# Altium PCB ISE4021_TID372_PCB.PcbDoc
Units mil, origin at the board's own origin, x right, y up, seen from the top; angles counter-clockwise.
Board outline 3700 x 2300 mil, 4 copper layers (Top Layer, Internal Plane 1, Mid-Layer 1, Bottom Layer), stack 62.1 mil thick; 57 components, 23 nets, 154 pads, 293 vias.
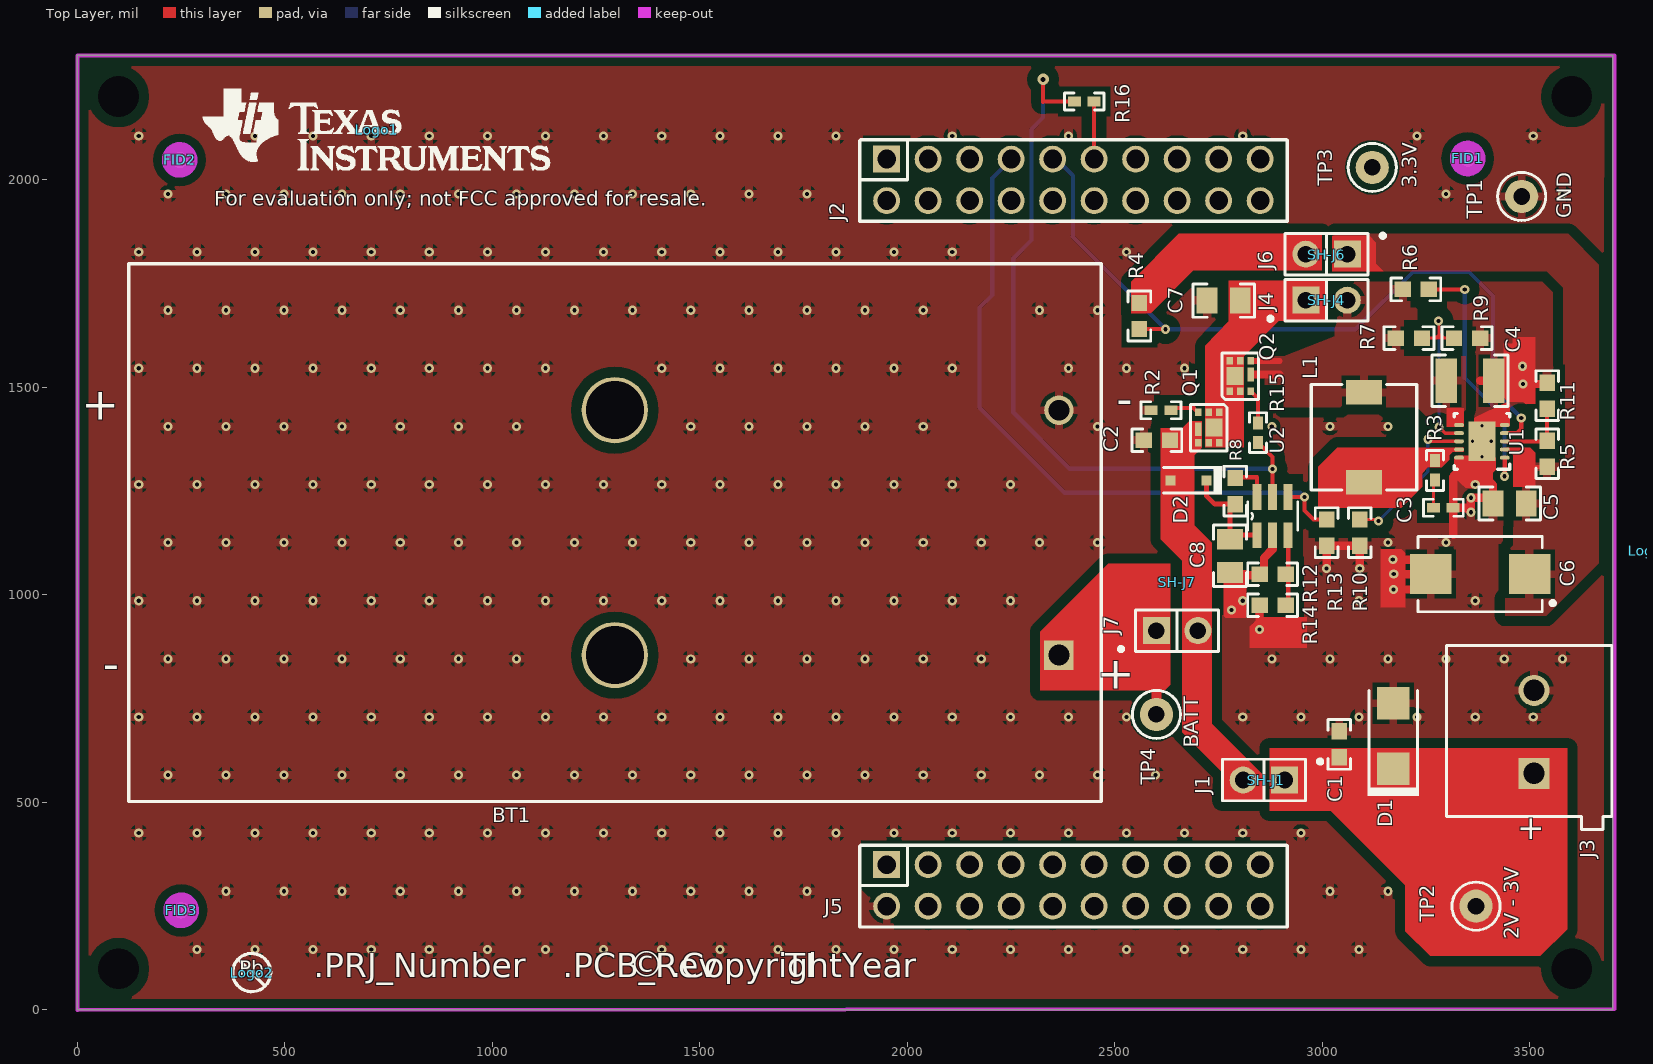
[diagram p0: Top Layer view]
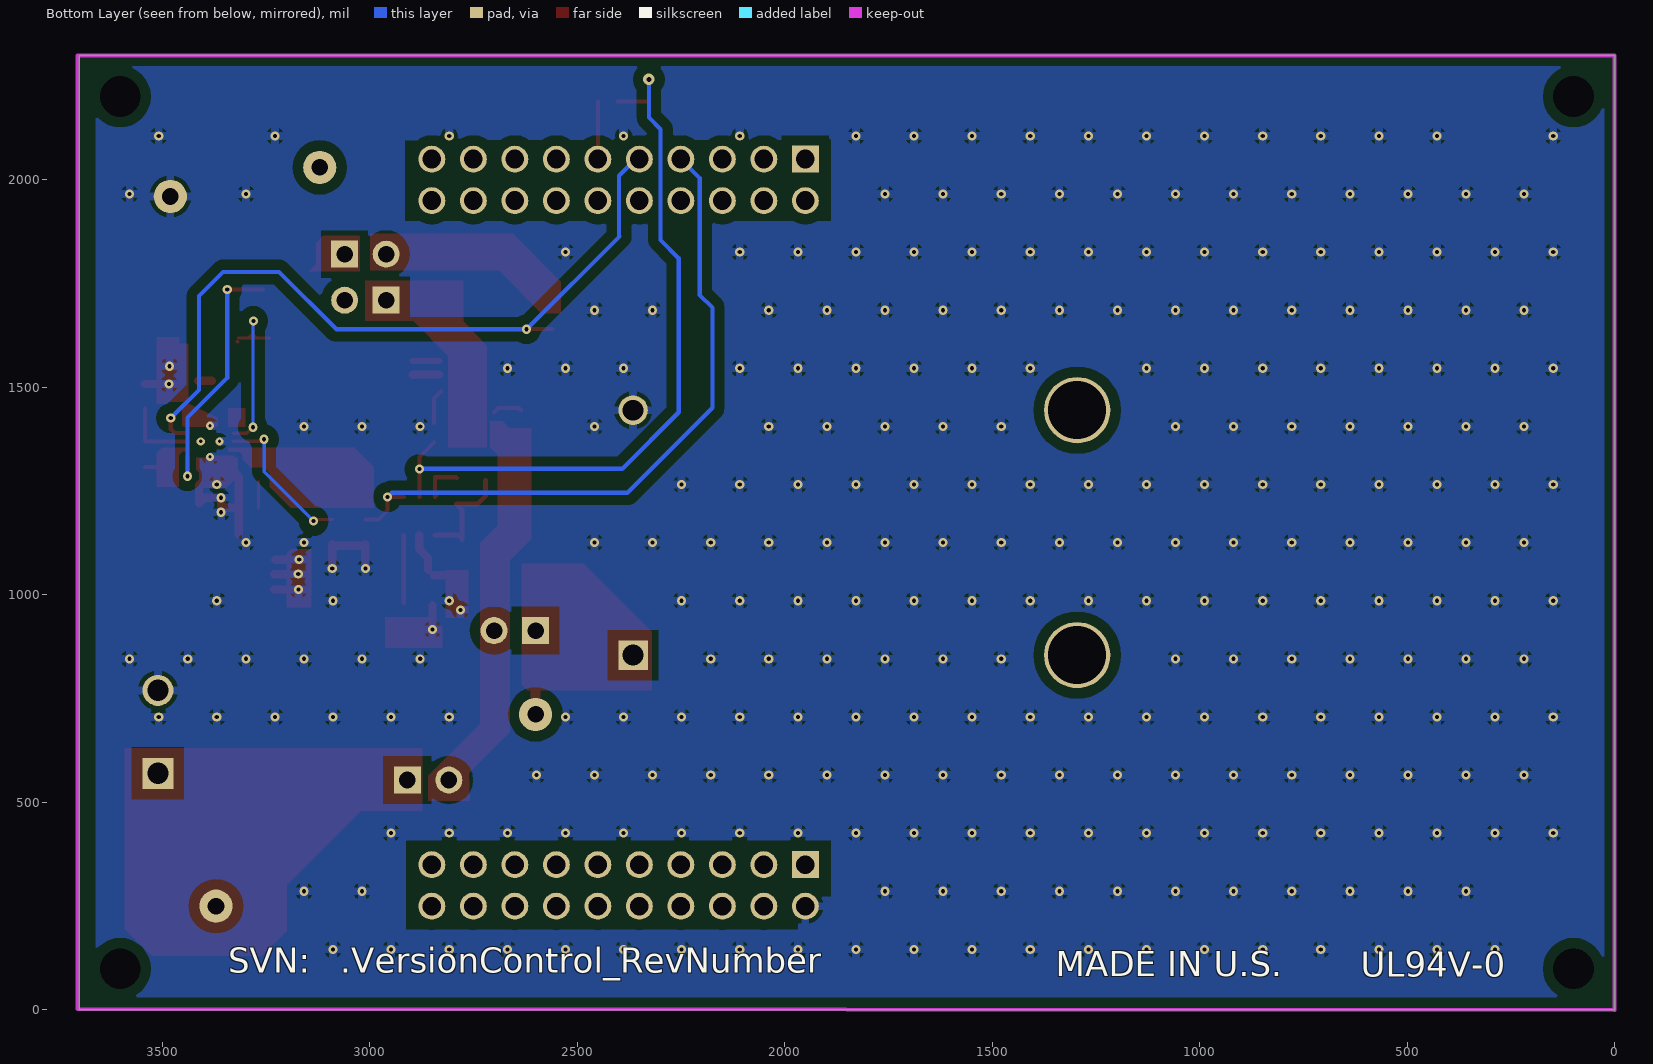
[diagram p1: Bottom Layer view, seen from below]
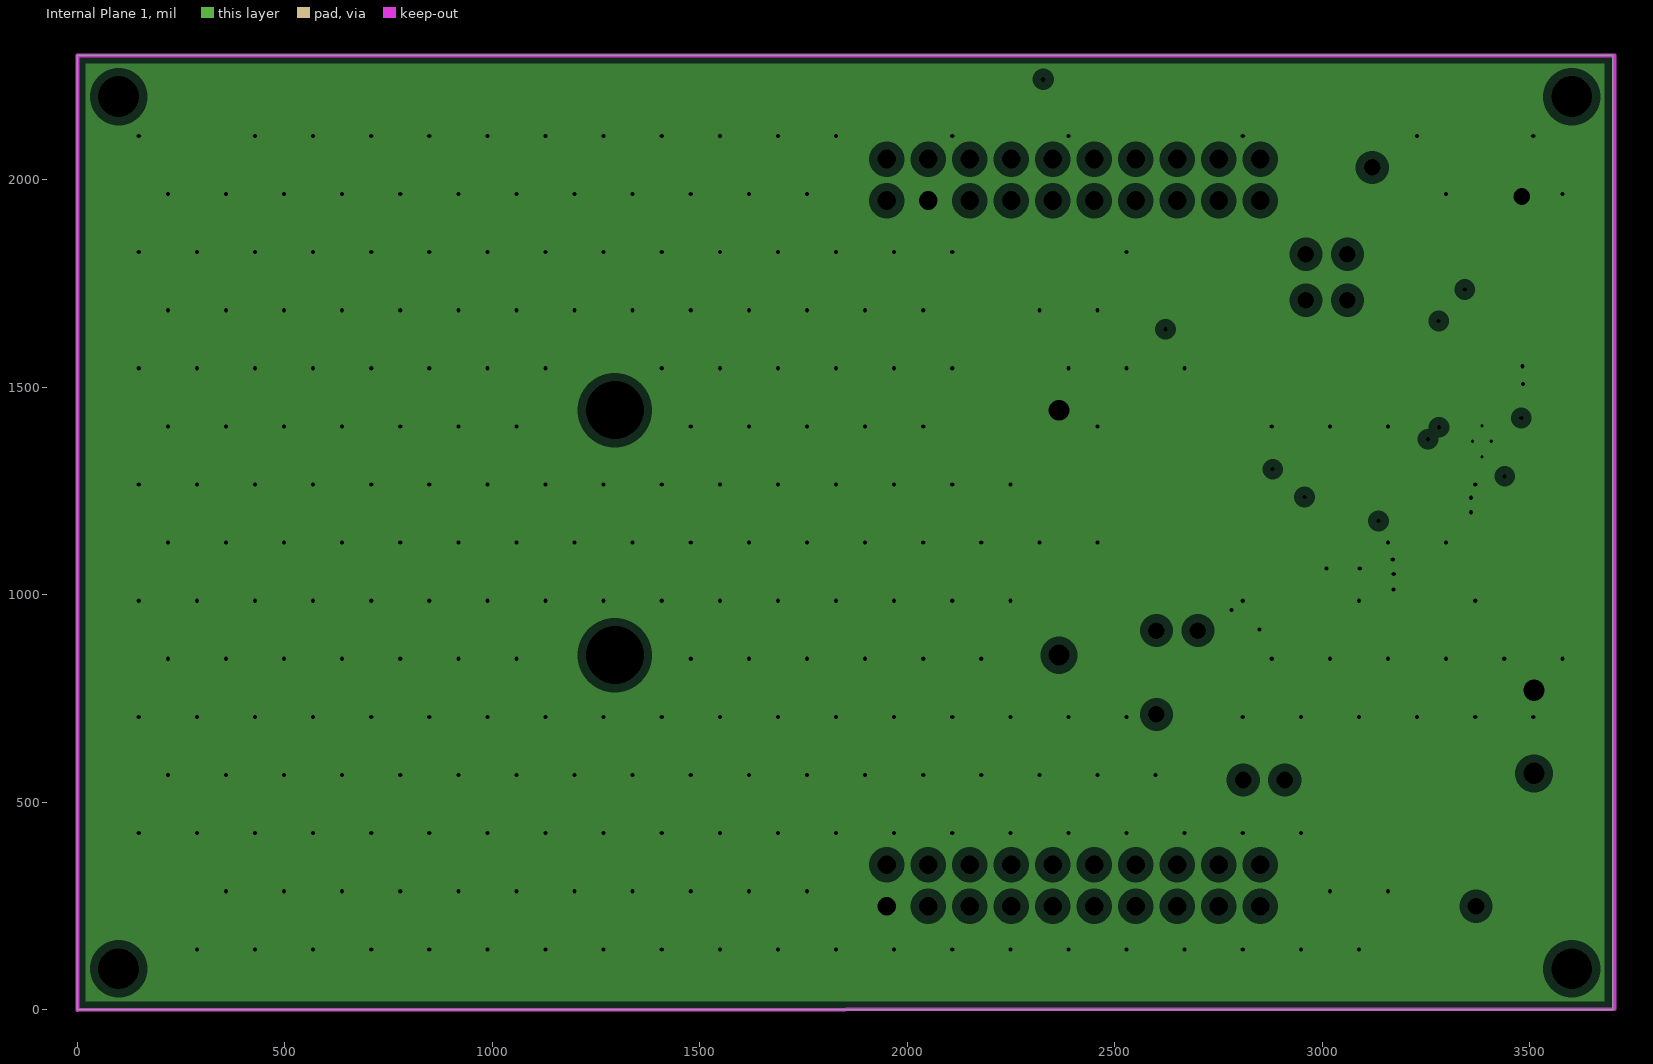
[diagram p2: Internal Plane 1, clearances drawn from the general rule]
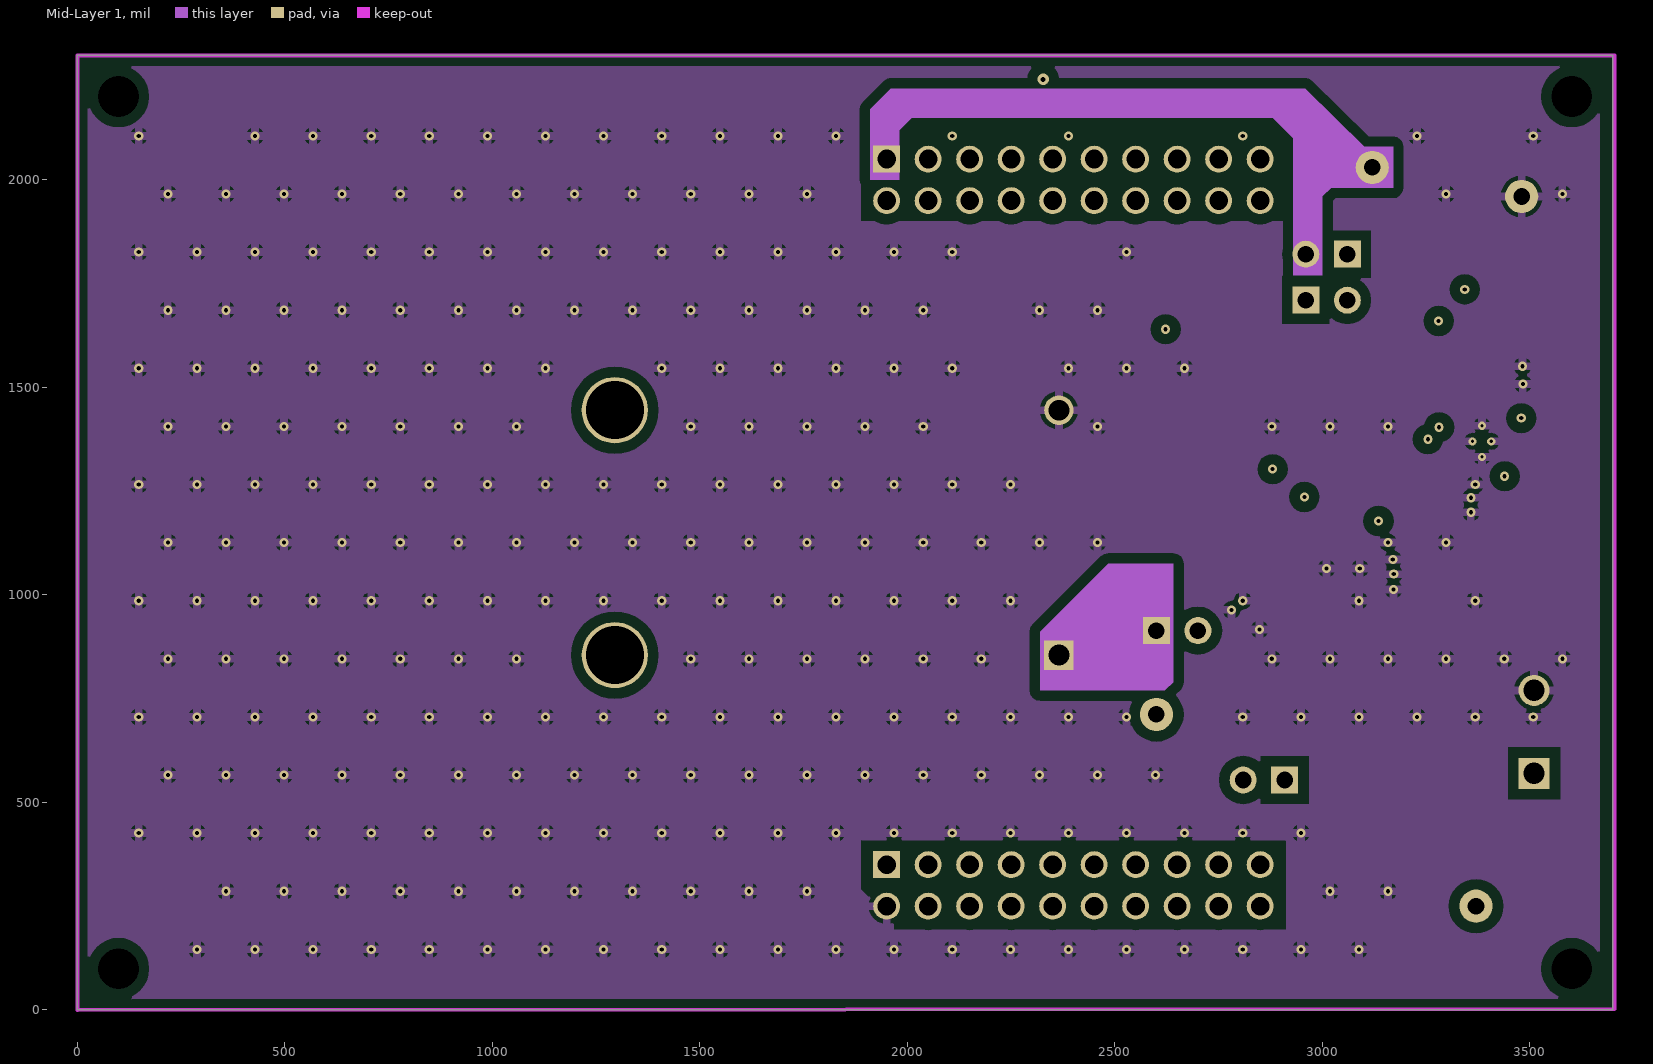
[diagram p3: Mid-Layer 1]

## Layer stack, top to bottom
Top Solder: solder mask 0.4, Solder Resist, Dk 3.5
Top Layer: signal copper 2
Dielectric1: core 9.65, FR-4 High Tg, Dk 4.8
Internal Plane 1: plane copper 1.4, net GND
Dielectric3: prepreg 36, FR-4 High Tg, Dk 4.8
Mid-Layer 1: signal copper 1.4
Dielectric2: core 9.65, FR-4 High Tg, Dk 4.8
Bottom Layer: signal copper 2
Bottom Solder: solder mask 0.4, Solder Resist, Dk 3.5

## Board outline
0,0 3700,0 3700,2300 0,2300

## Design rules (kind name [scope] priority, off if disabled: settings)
AcuteAngle [All] p1: minimum=4.50000000000000E+0001 checktracksonly=FALSE
AssemblyTestPointUsage [All] p1: valid=2
Clearance Clearance_BoardEdge_Poly [OnCopper and InPoly vs IsKeepOut] p1: gap=20
Clearance Clearance_BoardEdge_MountingHoles [OnCopper and InComponentClass('Mounting Holes') vs IsKeepOut] p2: gap=20
Clearance Clearance_Poly [InPolygon] p3: gap=25
Clearance Clearance_BoardEdge [OnCopper and Not InComponentClass('Logo') and not InComponentClass('FiducialMark') and not InRegion(1000,500,4000,800) vs IsKeepOut] p4: gap=20
Clearance [All] p5: gap=8
ComponentClearance ComponentClearance_MountingHoles_FiducialMarks [InComponentClass('Mounting Holes') vs InComponentClass('FiducialMark')] p1: gap=200 collisioncheckmode=3 verticalgap=10 showdistances=FALSE
ComponentClearance ComponentClearance_Shunt [InComponentClass('Header') vs InComponentClass('Shunt')] p2: gap=0 collisioncheckmode=3 verticalgap=0 showdistances=FALSE
ComponentClearance ComponentClearance_1 [All] p3: gap=10 collisioncheckmode=3 verticalgap=10 showdistances=FALSE
ComponentClearance ComponentClearance_Logo [InComponentClass(Logo)] p4 off: gap=50 collisioncheckmode=3 verticalgap=10 showdistances=FALSE
ComponentClearance ComponentClearance_ScrewToNut [(HasFootprint('NY PMS 440 0025 PH')) vs (HasFootprint('Keystone_1902C'))] p5 off: gap=5 collisioncheckmode=3 verticalgap=10 showdistances=FALSE
ComponentClearance ComponentClearance_MountingHoles [InComponentClass('Mounting Holes')] p6 off: gap=250 collisioncheckmode=3 verticalgap=100000 showdistances=FALSE
ComponentClearance ComponentClearance_SmallPassives [HasFootprint('0201*') or HasFootprint('0402*') or HasFootprint('0508') or HasFootprint('0603*') or HasFootprint('0612') or HasFootprint('0805*') or HasFootprint('0815*') or HasFootprint('0830*') or HasFootprint('1206*') or HasFootprint('1210*') or HasFootprint('1808*') or HasFootprint('1812*') or HasFootprint('1825*') or HasFootprint('2010*') or HasFootprint('2220*') or HasFootprint('2225*') or HasFootprint('2512*') or HasFootprint('2728*') or HasFootprint('3518*') vs HasFootprint('0201*') or HasFootprint('0402*') or HasFootprint('0508') or HasFootprint('0603*') or HasFootprint('0612') or HasFootprint('0805*') or HasFootprint('0815*') or HasFootprint('0830*') or HasFootprint('1206*') or HasFootprint('1210*') or HasFootprint('1808*') or HasFootprint('1812*') or HasFootprint('1825*') or HasFootprint('2010*') or HasFootprint('2220*') or HasFootprint('2225*') or HasFootprint('2512*') or HasFootprint('2728*') or HasFootprint('3518*')] p7 off: gap=20 collisioncheckmode=3 verticalgap=10 showdistances=FALSE
ComponentClearance ComponentClearance_THtoSMT [IsThruComponent vs IsSMTComponent] p8 off: gap=100 collisioncheckmode=3 verticalgap=100000 showdistances=FALSE
ComponentClearance ComponentClearance_THtoTH [IsThruComponent vs IsThruComponent] p9 off: gap=118.11 collisioncheckmode=3 verticalgap=100000 showdistances=FALSE
DiffPairsRouting [All] p1: maxlimit=100 minlimit=10 mostfreqgap=10 toplayer_minwidth=15 toplayer_maxwidth=15 toplayer_prefwidth=15 midlayer1_minwidth=15 midlayer1_maxwidth=15 midlayer1_prefwidth=15 bottomlayer_minwidth=15 bottomlayer_maxwidth=15 bottomlayer_prefwidth=15 maxuncoupledlength=1000
FabricationTestPointUsage TestPointUsage [All] p1: valid=2 allowmultiple=FALSE
FabricationTestpoint Testpoint [All] p1: side=3 testpointundercomponent=TRUE minsize=40 maxsize=100 preferedsize=60 minholesize=0 maxholesize=40 preferedholesize=32 testpointgrid=1 allowsidetop=TRUE allowsidebottom=TRUE usegrid=TRUE gridtolerance=0.01
FanoutControl Fanout_LCC [IsLCC] p1: bgadir=Out bgaviamode=Centered fanoutstyle=Auto fanoutdirection=Alternating viagrid=1 // Fanout_LCC (Default Rule)
FanoutControl Fanout_BGA [IsBGA] p2: bgadir=Out bgaviamode=Centered fanoutstyle=Auto fanoutdirection=Alternating viagrid=1 // Fanout_BGA (Default Rule)
FanoutControl Fanout_Default [All] p4: bgadir=Out bgaviamode=Centered fanoutstyle=Auto fanoutdirection=Alternating viagrid=1 // Fanout_Default (Default Rule)
FanoutControl Fanout_Small [(CompPinCount < 5)] p5: bgadir=Out bgaviamode=Centered fanoutstyle=Auto fanoutdirection=OutThenIn viagrid=1 // Fanout_Small (Default Rule)
HoleSize [All] p1: absolutevalues=TRUE maxlimit=550 minlimit=5 maxpercent=80.000 minpercent=20.000
MinimumAnnularRing MinimumAnnularRing_ThermalPadVias [IsVia and InAnyComponent] p1: minimumring=5.91
MinimumAnnularRing [All] p2: minimumring=6
MinimumSolderMaskSliver SilkscreenOverComponentPads [All] p1: minsoldermaskwidth=5.5
MinimumSolderMaskSliver MinimumSolderMaskSliver_Logo [InComponentClass('Logo') vs InComponentClass('Logo')] p2: minsoldermaskwidth=0.7
MinimumSolderMaskSliver [All] p3: minsoldermaskwidth=5
PlaneClearance [All] p1: clearance=20
PlaneConnect [All] p1: planeconnectstyle=Relief reliefexpansion=10 reliefentries=4 reliefconductorwidth=10 reliefairgap=10
PolygonConnect [All] p1: connectstyle=Relief reliefconductorwidth=20 reliefentries=4 polygonreliefangle="90 Angle" airgapwidth=10
RoutingVias ThermalPadVias [IsVia and InAnyComponent] p1: holewidth=7.87 width=19.68 viastyle="Through Hole" minholewidth=7.87 minwidth=19.68 maxholewidth=12.99 maxwidth=23.62
RoutingVias [All] p2: holewidth=12 width=28 viastyle="Through Hole" minholewidth=5 minwidth=20 maxholewidth=100 maxwidth=150
SMDToCorner [All] p1: distance=30000
SilkToSilkClearance SilkToSilkClearance_Pb-FreeLogo [(HasFootprint('Pb-Free_Overlay_Medium') OR HasFootprint('Pb-Free_Overlay_Small')) vs (HasFootprint('Pb-Free_Overlay_Medium') OR HasFootprint('Pb-Free_Overlay_Small'))] p1: silktosilkclearance=0
SilkToSilkClearance [All] p2: silktosilkclearance=5
SilkToSolderMaskClearance "Silk to Solder Mask Opening" [IsPad] p1: minsilkscreentomaskgap=1 clearancetoexposedcopper=TRUE
SolderMaskExpansion [All] p1: expansion=3
UnpouredPolygon [All] p1: allowunpoured=FALSE
Width [All] p1: maxlimit=100 minlimit=6 preferedwidth=10 checkconnectedcopper=TRUE
14 further rules are at their usual default settings.

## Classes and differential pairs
component class Logo: Logo1
component class FiducialMark: FID1 FID2 FID3
component class AssemblyNote: ZZ1 ZZ2 ZZ3 ZZ4 ZZ5
component class Header: J1 J4 J6 J7
component class Shunt: SH-J1 SH-J4 SH-J6 SH-J7

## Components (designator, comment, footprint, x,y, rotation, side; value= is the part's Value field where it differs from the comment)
BT1 "2462" Keystone_2462 1830,1150 r180 top
C1 "06033C104JAT2A" 0603 3040.63,640 r90 top
C2 "06033C104JAT2A" 0603 2601,1373 r180 top
C3 "C1005C0G1E102J" 0402 3291.3,1210 r0 top
C4 "GRM32ER61C476KE15L" 1210 3355.5,1515.95 r0 top
C5 "C2012X5R1A225K/0.85" 0805_HV 3450.98,1220 r180 top
C6 "T495D476K020ATE100" 7343-31 3380,1050 r180 top
C7 "C2012X5R1E106K125AB" 0805_HV 2762,1709 r180 top
C8 "GRM216R61E105KA12D" 0805_HV 2777,1094 r90 top
D1 "SMAJ5.0CA" SMA 3170.63,660 r90 top
D2 "1SS315TPH3F" sod-323 2677,1276 r180 top
FID1 "Fiducial" Fiducial10-20 3350,2051.5 r0 top
FID2 "Fiducial" Fiducial10-20 246.5,2048 r0 top
FID3 "Fiducial" Fiducial10-20 250,240 r0 top
J1 "90120-0122" CONN_90120-0122 2859,554 r180 top
J2 "SSW-110-23-F-D" CONN_SSW-110-23-F-D 2400,2000 r180 top
J3 "1715721" PhoenixContact_1715721 3510,670 r90 top
J4 "90120-0122" CONN_90120-0122 3010,1710 r0 top
J5 "SSW-110-23-F-D" CONN_SSW-110-23-F-D 2400,300 r180 top
J6 "90120-0122" CONN_90120-0122 3010,1821 r180 top
J7 "90120-0122" CONN_90120-0122 2650,914 r0 top
L1 "SLF6028T-6R8M1R5-PF" SLF6028 3100,1380 r270 top
Logo1 "Texas Instruments" TI_Stacked_Overlay_Small 721,2121 r0 top
Logo2 "Pb-Free Symbol" Pb-Free_Overlay_Small 420,90 r0 top
Logo3 "FCC disclaimer" FCC_disclaimer 3788,1106 r90 top
Q1 "CSD25310Q2" TRANS_NexFET_Q2 2726,1403 r270 top
Q2 "CSD25310Q2" TRANS_NexFET_Q2 2802,1527 r90 top
R2 "CRCW0402200KFKED" 0402 2611,1445 r0 top
R3 "CRCW04021K00FKED" 0402 3271.3,1300 r90 top
R4 "CRCW06031M00FKEA" 0603 2559,1672 r90 top
R5 "CRCW06031M00FKEA" 0603 3541.3,1340 r270 top
R6 "CRCW06030000Z0EA" 0603 3225,1736 r0 top
R7 "CRCW06031M00FKEA" 0603 3208.5,1618.95 r180 top
R8 "CRCW0603100KFKEA" 0603 2790,1250 r270 top
R9 "CRCW0603392KFKEA" 0603 3348.5,1618.95 r180 top
R10 "CRCW06030000Z0EA" 0603 3090,1150 r90 top
R11 "CRCW0603178KFKEA" 0603 3541.3,1480 r270 top
R12 "CRCW060340K2FKEA" 0603 2880,1050 r0 top
R13 "CRCW06032K67FKEA" 0603 3010,1150 r90 top
R14 "CRCW060348K7FKEA" 0603 2880,974.97 r0 top
R15 "CRCW04020000Z0ED" 0402 2845,1391 r90 top
R16 "CRCW04020000Z0ED" 0402 2426,2189 r180 top
SH-J1 "2SN-BK-G" 2SN-BK-G 2864,554 r180 top
SH-J4 "2SN-BK-G" 2SN-BK-G 3010,1710 r0 top
SH-J6 "2SN-BK-G" 2SN-BK-G 3010,1820 r180 top
SH-J7 "2SN-BK-G" 2SN-BK-G 2650,1030 r0 top
TP1 "5001" Keystone5001 3480,1960 r180 top
TP2 "5000" Keystone5000 3370,250 r90 top
TP3 "5000" Keystone5000 3120,2030 r0 top
TP4 "5000" Keystone5000 2600,712 r180 top
U1 "TPS61029DRCR" DRC0010A 3384.21,1370 r180 top
U2 "TPL5110DDC" DDC0006A_N 2880,1190 r90 top
ZZ1 "These assemblies are ESD sensitive, ESD precautions shall be observed." AssemblyNote 190,3830 r0 top
ZZ2 "These assemblies must be clean and free from flux and all contaminants. Use of no clean flux is not acceptable." AssemblyNote 190,3740 r0 top
ZZ3 "These assemblies must comply with workmanship standards IPC-A-610 Class 2, unless otherwise specified." AssemblyNote 190,3650 r0 top
ZZ4 "Place SH-J1 on J1, SH-J4 on J4, SH-J6 on J6 and SH-J7 on J7 (pins 1-2)." AssemblyNote 190,3560 r0 top
ZZ5 "J2 and J5 must NOT have the lead ends trimmed off." AssemblyNote 190,3460 r0 top

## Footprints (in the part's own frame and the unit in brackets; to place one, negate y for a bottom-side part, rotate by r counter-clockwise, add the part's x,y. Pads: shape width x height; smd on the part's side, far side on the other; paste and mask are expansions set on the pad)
2SN-BK-G [mil] "Samtec STEP model"
  round 1 on Mech3: 0(0,0)
  body extent -78,-39 79,39, height 188
0402 [mm] "0402 from SM-752 data"
  rect 0.8x0.6 smd: 1(-0.6,0) 2(0.6,0)
  silkscreen extent -1.22,-0.52 1.22,0.52, body extent -0.55,-0.3 0.55,0.3, height 0.6
0603 [mm] "0603 from SM-752 data"
  rect 1x0.95 smd: 1(-0.8,0) 2(0.8,0)
  silkscreen extent -1.52,-0.69 1.52,0.69, body extent -0.87,-0.47 0.87,0.47, height 0.85
0805_HV [mil] "0805 with 30mil clearance between pads"
  rect 50x63 smd: 1(-40,0) 2(40,0)
  silkscreen extent -74,-40 74,40, body extent -43,-29 43,29, height 43
1210 [mm] "1210 from SM-752 data"
  rect 1.3x2.7 smd: 1(-1.45,0) 2(1.45,0)
  silkscreen extent -2.32,-1.57 2.32,1.57, body extent -1.7,-1.35 1.7,1.35, height 1.35
7343-31 [mm] "Medium Density based on Kemet T495 dimensions"
  rect 2.55x2.45 smd: 1(-3.025,0) 2(3.025,0)
  silkscreen extent -4.56,-2.3 3.8,2.3, body extent -3.8,-2.3 3.8,2.3, height 3.1
AssemblyNote [mil] "Assembly Note"
CONN_90120-0122 [mm] "Molex"
  rect 1.65x1.65 hole 1.016 mask+0: 1(-1.27,0)
  round 1.65 hole 1.016 mask+0: 2(1.27,0)
  silkscreen extent -3.57,-1.27 2.54,1.27, body extent -2.54,-1.27 2.54,1.27, height 9.29
CONN_SSW-110-23-F-D [mm] "SAMTEC"
  rect 1.65x1.65 hole 1.15: 1(11.43,-1.27)
  round 1.65 hole 1.15: 2(11.43,1.27) 3(8.89,-1.27) 4(8.89,1.27) 5(6.35,-1.27) 6(6.35,1.27) 7(3.81,-1.27) 8(3.81,1.27) 9(1.27,-1.27) 10(1.27,1.27) 11(-1.27,-1.27) 12(-1.27,1.27) 13(-3.81,-1.27) 14(-3.81,1.27) 15(-6.35,-1.27) 16(-6.35,1.27) 17(-8.89,-1.27) 18(-8.89,1.27) 19(-11.43,-1.27) 20(-11.43,1.27)
  silkscreen extent -13.08,-2.46 13.08,2.54, body extent -13,-2.51 13,2.54, height 8.59
DDC0006A_N [mil]
  rect 62x22 smd: 1(-46,37.4) 2(-46,0) 3(-46,-37.4) 4(46,-37.4) 5(46,0) 6(46,37.4)
  silkscreen extent -35,-60 35,60, body extent -56,-58 56,58, height 35
DRC0010A [mm] "SON, 10-Leads, Body 3x3mm, Pitch 0.5mm, Thermal Pad 2.4x1.65mm, TI Recommended"
  oval 0.6x0.24 smd mask+0: 1(-1.4,1) 2(-1.4,0.5) 3(-1.4,0) 4(-1.4,-0.5) 5(-1.4,-1) 6(1.4,-1) 7(1.4,-0.5) 8(1.4,0) 9(1.4,0.5) 10(1.4,1)
  rect 1.65x2.4 smd paste-0.825: 11(0,0)
  Top Layer region: 0.135,1.1 0.365,1.1 0.365,1.5 0.135,1.5
  Top Layer region: -0.135,1.5 -0.365,1.5 -0.365,1.1 -0.135,1.1
  Top Layer region: -0.135,-1.1 -0.365,-1.1 -0.365,-1.5 -0.135,-1.5
  Top Layer region: 0.135,-1.5 0.365,-1.5 0.365,-1.1 0.135,-1.1
  silkscreen extent -1.7,-1.7 1.7,1.7, body extent -1.55,-1.55 1.55,1.55, height 1.01
FCC_disclaimer [mil]
Fiducial10-20 [mm]
  round 1 smd mask+0.5: 1(0,0)
  Top Layer keep-out circle w1.178: c0,0 r0.5
Keystone5000 [mil] "For Keystone 500x miniature loop terminals"
  round 80 hole 40: 1(0,0)
  silkscreen extent -58,-58 58,58, body extent -49,-49 49,49, height 182
Keystone5001 [mil] "For Keystone 500x miniature loop terminals"
  round 80 hole 40: 1(0,0)
  silkscreen extent -58,-58 58,58, body extent -49,-49 49,49, height 182
Keystone_2462 [mm] "2x AA Battery Holder, Through-hole mount"
  rect 1.8x1.8 hole 1.27: 1(-13.59,7.495)
  round 1.8 hole 1.27: 2(-13.59,-7.495)
  round 4.05 hole 3.55: 3(13.59,-7.495) 4(13.59,7.495)
  silkscreen extent -16.18,-16.46 43.33,16.46, body extent -16.31,-16.46 43.4,16.46, height 16
Pb-Free_Overlay_Small [mil]
  silkscreen extent -46,-46 46,46
PhoenixContact_1715721 [mm] "Phoenix Contact 1715721 used on LM3445 design from Longmont"
  rect 1.905x1.905 hole 1.3: 1(-2.54,0)
  round 1.9 hole 1.3: 2(2.54,0)
  silkscreen extent -5.97,-4.75 5.28,5.36, body extent -5.82,-4.6 5.08,5.2, height 14.2
SLF6028 [mm] "TDK"
  rect 1.5x2.2 smd: 1(-2.75,0) 2(2.75,0)
  silkscreen extent -3.22,-3.22 3.22,3.22, body extent -3.1,-3.1 3.1,3.1, height 3
SMA [mm] "Molded Diode, 2-Leads, Body 4.3x2.6mm, IPC Medium Density, based on OnSemi component dimensions and land pattern"
  rect 2x2 smd: 1(-2,0) 2(2,0)
  silkscreen extent -3.66,-1.57 2.79,1.57, body extent -2.6,-1.3 2.6,1.3, height 2.42
sod-323 [mm] "NXP recommended land pattern"
  rect 0.6x0.6 smd paste-0.05: 1(-1.1,0) 2(1.1,0)
  silkscreen extent -2.06,-0.86 1.53,0.86, body extent -1.3,-0.67 1.3,0.68, height 1.1
TI_Stacked_Overlay_Small [mil]
  silkscreen extent -418,-98 418,98
TRANS_NexFET_Q2 [mm] "TI recommended land pattern M0167-01"
  rect 0.46x0.4 smd mask+0: 1(-0.93,0.65) 2(-0.93,0) 3(-0.93,-0.65) 4(0.93,-0.65) 5(0.93,0) 6(0.93,0.65)
  rect 0.85x0.4 smd paste-0.025 mask+0: 7(0.095,-0.65)
  rect 1.1x1.05 smd paste-0.05 mask+0: 8(0,0.325)
  silkscreen extent -1.43,-1.12 1.43,1.12, body extent -1,-1 1,1, height 0.85

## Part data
BT1: "2x AA Battery Holder, Through-hole mount"
C1 C2: "CAP, CERM, 0.1 µF, 25 V, +/- 5%, X7R, 0603"
C3: "CAP, CERM, 1000 pF, 25 V, +/- 5%, C0G/NP0, 0402"
C4: "CAP, CERM, 47 µF, 16 V, +/- 10%, X5R, 1210"
C5: "CAP, CERM, 2.2 µF, 10 V, +/- 10%, X5R, 0805"
C6: "CAP, TA, 47 µF, 20 V, +/- 10%, 0.1 ohm, SMD"
C7: "CAP, CERM, 10 µF, 25 V, +/- 10%, X5R, 0805"
C8: "CAP, CERM, 1 µF, 25 V, +/- 10%, X5R, 0805"
D1: "Diode, TVS, Bi, 5 V, 400 W, SMA"
D2: "Diode, Schottky, 5 V, 0.03 A, SOD-323"
FID1 FID2 FID3: "Fiducial mark.  There is nothing to buy or mount."
J1 J4 J6 J7: "Header, 100mil, 2x1, Tin, TH"
J2 J5: "Connector, Receptacle, 100mil, 10x2, Gold plated, TH"
J3: "Conn Term Block, 2POS, 5.08mm, TH"
L1: "Inductor, Shielded Drum Core, Ferrite, 6.8 µH, 1.5 A, 0.0354 ohm, SMD"
Logo1: library part TI_Logo, "Texas Instrument Corporate Signature"
Logo2: library part Pb-Free
Logo3: library part FCC_disclaimer, "FCC_disclaimer"
Q1 Q2: "MOSFET, P-CH, -20 V, -20 A, SON 2x2mm"
R2: "RES, 200 k, 1%, 0.063 W, 0402"
R3: "RES, 1.00 k, 1%, 0.063 W, 0402"
R4 R5 R7: "RES, 1.00 M, 1%, 0.1 W, 0603"
R6 R10: "RES, 0, 5%, 0.1 W, 0603"
R8: "RES, 100 k, 1%, 0.1 W, 0603"
R9: "RES, 392 k, 1%, 0.1 W, 0603"
R11: "RES, 178 k, 1%, 0.1 W, 0603"
R12: "RES, 40.2 k, 1%, 0.1 W, 0603"
R13: "RES, 2.67 k, 1%, 0.1 W, 0603"
R14: "RES, 48.7 k, 1%, 0.1 W, 0603"
R15 R16: "RES, 0, 5%, 0.063 W, 0402"
SH-J1 SH-J4 SH-J6 SH-J7: "Shunt, 2mm, Gold plated, Black"
TP1: "Test Point, Miniature, Black, TH"
TP2 TP3 TP4: "Test Point, Miniature, Red, TH"
U1: "Adjustable, 1.8-A Switch, 96% Efficient Boost Converter with Down-Mode, DRC0010A"
U2: "Ultra-Low Power System Timer with MOS driver and manual MSFET power ON, DDC0006A"
ZZ1 ZZ2 ZZ3 ZZ4 ZZ5: library part AssemblyNote

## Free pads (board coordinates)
  round 49.21 hole 98.43 paste+0 mask+0: 0(99.21,99.21) 0(99.21,2200.79) 0(3600.79,99.21) 0(3600.79,2200.79)

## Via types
v1: diameter 22, hole 10, Top Layer to Bottom Layer, tented both sides, 267 vias
v2: diameter 22, hole 10, Top Layer to Bottom Layer, 21 vias
v3: diameter 19.68, hole 7.87, Top Layer to Bottom Layer, 4 vias
v4: diameter 28, hole 12, Top Layer to Bottom Layer, 1 vias

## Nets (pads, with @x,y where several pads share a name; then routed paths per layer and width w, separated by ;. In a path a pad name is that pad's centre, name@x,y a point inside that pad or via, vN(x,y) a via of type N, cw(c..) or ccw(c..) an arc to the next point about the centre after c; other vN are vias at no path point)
3V3_OUT: C5.1 C6.1 J6.1 R5.2 U1.2 | length 119.3
  Top Layer w10: U1.2 3469.69,1350.31 3511.5,1308.5 R5.2
+3V3: J2.1 J6.2 R4.2 TP3.1
DONE: J2.7 R13.2 U2.4 | length 1636.2
  Top Layer w10: U2.4 v2(2956.48,1236) 2956.48,1203.52 2978.5,1181.5 R13.2
  Bottom Layer w10: J2.7 2204.52,2004.52 2204.52,1722.52 2174,1692 2174,1451 2379,1246 2946.48,1246 v2(2956.48,1236)
DRV: R15.1 R16.2 U2.5 | length 1789.2
  Top Layer w10: v4(2327,2242) 2327,2188 2328,2189 R16.2 ; R15.1 2880,1332.38 v2(2880,1303) U2.5
  Bottom Layer w10: v4(2327,2242) 2327,2150 2299,2122 2299,1855 2255,1811 2255,1440 2391,1304 2879,1304 v2(2880,1303)
DRV_1: J2.11 R16.1 | length 139.2
  Top Layer w10: R16.1 2449.62,2050.38 J2.11
FB: R5.1 R11.2 U1.3 | length 179.6
  Top Layer w10: U1.3 3539.8,1370 R5.1 R11.2
GND: BT1.2 C1.2 C2.2 C3.2 C4.2 C5.2 C6.2 C7.2 C8.1 D1.2 J2.4 J3.2 J5.2 R2.1 R9.1 R10.1 R11.1 R12.1 R13.1 R14.1 TP1.1 U1.5 U1.10 U1.11 U2.2 | length 1153.5
  Top Layer w10: U1.10 U1.11@3384.21,1330.63 ; U1.11@3384.21,1409.37 U1.5
  Top Layer w20: C8.1@2787.09,1047 R12.1@2845.55,1047 ; v2(2848.51,916.51) R14.1 ; R12.1@2859,1060.49 2859,1089 2880,1110 U2.2 ; v2(3010,1063.48) R13.1@3010,1121.95 ; R13.1 R10.1 ; v2(3090,1063.48) R10.1@3090,1121.95 ; v2(3169.53,1085) C6.2@3228,1085 ; v2(3171.53,1013) C6.2@3230,1013 ; v2(3171.93,1050) C6.2@3230.39,1050 ; 3314.92,1144.92 C3.2 ; 3314.92,1283.92 C3.2 ; 3380,1516 3380.05,1515.95 C4.2 ; 3398.55,1305.16 3401,1302.71 3401,1274.99 3410.98,1265 C5.2 3396.98,1234 v2(3357.53,1234) v2(3357.53,1199) 3346.53,1210 C3.2 ; v2(3482.83,1508.05) R11.1@3541.3,1508.05
  other v1: 288,146 428,146 568,146 708,146 848,146 988,146 1128,146 1268,146 1408,146 1548,146 1688,146 1828,146 1968,146 2108,146 2248,146 2388,146 2528,146 2668,146 2808,146 2948,146 3088,146 358,286 498,286 638,286 778,286 918,286 1058,286 1198,286 1338,286 1478,286 1618,286 1758,286 3018,286 3158,286 148,426 288,426 428,426 568,426 708,426 848,426 988,426 1128,426 1268,426 1408,426 1548,426 1688,426 1828,426 1968,426 2108,426 2248,426 2388,426 2528,426 2668,426 2808,426 2948,426 218,566 358,566 498,566 638,566 778,566 918,566 1058,566 1198,566 1338,566 1478,566 1618,566 1758,566 1898,566 2038,566 2178,566 2318,566 2458,566 2598,566 148,706 288,706 428,706 568,706 708,706 848,706 988,706 1128,706 1268,706 1408,706 1548,706 1688,706 1828,706 1968,706 2108,706 2248,706 2388,706 2528,706 2808,706 2948,706 3088,706 3228,706 3368,706 3508,706 218,846 358,846 498,846 638,846 778,846 918,846 1058,846 1478,846 1618,846 1758,846 1898,846 2038,846 2178,846 2878,846 3018,846 3158,846 3298,846 3438,846 3578,846 148,986 288,986 428,986 568,986 708,986 848,986 988,986 1128,986 1268,986 1408,986 1548,986 1688,986 1828,986 1968,986 2108,986 2248,986 2808,986 3088,986 3368,986 218,1126 358,1126 498,1126 638,1126 778,1126 918,1126 1058,1126 1198,1126 1338,1126 1478,1126 1618,1126 1758,1126 1898,1126 2038,1126 2178,1126 2318,1126 2458,1126 3158,1126 3298,1126 148,1266 288,1266 428,1266 568,1266 708,1266 848,1266 988,1266 1128,1266 1268,1266 1408,1266 1548,1266 1688,1266 1828,1266 1968,1266 2108,1266 2248,1266 3368,1266 218,1406 358,1406 498,1406 638,1406 778,1406 918,1406 1058,1406 1478,1406 1618,1406 1758,1406 1898,1406 2038,1406 2458,1406 2878,1406 3018,1406 3158,1406 148,1546 288,1546 428,1546 568,1546 708,1546 848,1546 988,1546 1128,1546 1408,1546 1548,1546 1688,1546 1828,1546 1968,1546 2108,1546 2388,1546 2528,1546 2668,1546 218,1686 358,1686 498,1686 638,1686 778,1686 918,1686 1058,1686 1198,1686 1338,1686 1478,1686 1618,1686 1758,1686 1898,1686 2038,1686 2318,1686 2458,1686 148,1826 288,1826 428,1826 568,1826 708,1826 848,1826 988,1826 1128,1826 1268,1826 1408,1826 1548,1826 1688,1826 1828,1826 1968,1826 2108,1826 2528,1826 218,1966 358,1966 498,1966 638,1966 778,1966 918,1966 1058,1966 1198,1966 1338,1966 1478,1966 1618,1966 1758,1966 3298,1966 3578,1966 148,2106 428,2106 568,2106 708,2106 848,2106 988,2106 1128,2106 1268,2106 1408,2106 1548,2106 1688,2106 1828,2106 2108,2106 2388,2106 2808,2106 3228,2106 3508,2106
  other v2: 2781,964 3481.77,1551
  other v3: 3384.21,1332.6 3361.57,1370 3406.85,1370 3384.21,1407.4
LBI: R7.1 R9.2 U1.7 | length 451
  Top Layer w8: R7.1 3281,1618.95 R9.2 ; 3273,1619 3281,1627 v2@3281,1667.05 ; v2(3281,1404) 3295.32,1389.68 U1.7 ; 3283,1627 3292,1618.95 ; R9.2@3317,1610 R9.2@3318.5,1610
  Bottom Layer w8: v2(3281,1404) v2@3281,1659
  other v2: 3280,1660
NetR6_2: R6.2 U1.1 | length 621
  Top Layer w10: R6.2 v2(3343,1736) ; v2(3439,1286) 3439,1296 3439.33,1296.33 U1.1
  Bottom Layer w10: v2(3343,1736) 3343,1523 3439,1427 v2(3439,1286)
NetR8_1: R8.1 U2.6 | length 106.5
  Top Layer w10: R8.1 2791.9,1283.4 2842.6,1283.4 U2.6 U2.6@2838.56,1240.03
NetR10_2: R10.2 U1.8 | length 369.9
  Top Layer w8: R10.2 3131.5,1181.5 v2(3135,1178) ; v2(3254,1375) 3259,1370 U1.8
  Bottom Layer w8: v2(3135,1178) 3254,1297 v2(3254,1375)
NetR12_2: R12.2 R14.2 U2.3 | length 163.1
  Top Layer w10: R14.2@2917.4,980.88 U2.3
NLOWBATT: J2.9 R4.1 U1.4 | length 1848.5
  Top Layer w10: R4.1 2621.5,1640.5 v2(2622,1640) ; U1.4 3468.69,1389.68 3479,1400 v2(3479,1426)
  Bottom Layer w10: J2.9@2350,2036 2373,2036 2399,2010 2399,1865 2398,1864 v2(2622,1640) 3080,1640 3218,1778 3353,1778 3411,1720 3411,1494 v2(3479,1426)
PGATE: Q2.3 R15.2 | length 83
  Top Layer w10: Q2.3 2845,1472.98 R15.2
SN: C3.1 R3.1 | length 62.8
  Top Layer w8: C3.1 R3.1@3267.68,1272.76
U2_SW: L1.2 R3.2 U1.9
V_GATES: Q1.3 R2.2 | length 73
  Top Layer w10: R2.2 2640.04,1450.41 2690.41,1450.41 2690.41,1449.61 Q1.3
V_INPUT: C1.1 D1.1 J1.1 J3.1 TP2.1
V_Q1Q2: C7.1 J4.1 Q1.1 Q1.2 Q1.5 Q1.6 Q1.8 Q2.1 Q2.2 Q2.5 Q2.6 Q2.8 | length 2
  Top Layer w10: J4.1@2960,1708 J4.1
V_TPL: C8.2 D2.1 R8.2 U2.1 | length 275
  Top Layer w12: D2.1 2721,1275.31 2721,1238.01 2740.5,1218.5 R8.2 2777,1205.5 C8.2 2787,1144 U2.1
VBATT: BT1.1 J7.1 TP4.1 | length 87.9
  Top Layer w25: 2593,797 2600,790 TP4.1
VBATT_SWITCHED: C4.1 J4.2 L1.1 Q2.4 Q2.7 R6.1 R7.2 U1.6 | length 127.7
  Top Layer w15: Q2.4@2832,1563.87 2895.84,1563.61
  Top Layer w20: Q2.7@2832,1531 2895.84,1530.74
VIN2: C2.1 D2.2 J1.2 J7.2 Q1.4 Q1.7
pads on no net: BT1.3 BT1.4 FID1.1 FID2.1 FID3.1 J2.2 J2.3 J2.5 J2.6 J2.8 J2.10 J2.12 J2.13 J2.14 J2.15 J2.16 J2.17 J2.18 J2.19 J2.20 J5.1 J5.3 J5.4 J5.5 J5.6 J5.7 J5.8 J5.9 J5.10 J5.11 J5.12 J5.13 J5.14 J5.15 J5.16 J5.17 J5.18 J5.19 J5.20 SH-J1.0 SH-J4.0 SH-J6.0 SH-J7.0

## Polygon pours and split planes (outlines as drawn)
GND on Top Layer "Top Layer-No Net" (solid, remove dead copper, pour order 21): 27,2289.8 27,0 3690,0 3690,2279.9
VBATT_SWITCHED on Top Layer "Top Layer-No Net 1" (solid, remove dead copper, pour order 20): 2818.16,1575 2818.16,1506 2907.16,1506 2907.16,1452 3228.16,1452 3251.1,1429.05 3345,1429.06 3345,1582 3228.16,1582 3228.16,1744 3208.89,1763.27 3029.16,1763.27 3029.16,1622.9 2907.16,1575
3V3_OUT on Top Layer "Top Layer-No Net 2" (solid, remove dead copper, pour order 17): 3434.57,1345 3460,1345 3460,1120 3440,1100 3440,949.61 3539.61,949.61 3666,1076 3666,1796 3592,1870 3021.57,1870 3020,1780 3540,1780 3580,1740 3580,1329 3513,1329 3485,1356 3434,1355
GND on Bottom Layer "Top Layer-No Net" (solid, remove dead copper, pour order 19): 0,2300 0,31 3660,31 3660,2290.11
GND on Mid-Layer 1 "Top Layer-No Net" (solid, remove dead copper, pour order 18): 0.49,2299.05 0.49,21 3668,21 3668,2289.14
GND on Internal Plane 1 (split plane): 3679.9,20.1 20.1,20.1 20.1,2279.9 3679.9,2279.9

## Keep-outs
Keep-Out Layer:
  lines w10: 0,2299 3704,2300 3703,2.07 0,0.07 0,2300

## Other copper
Top Layer:
  region net 3V3_OUT: 3442.51,1353.49 3460,1336 3459.99,1260 3513,1260 3513,1343 3501,1355 3444.02,1355
  region net VIN2: 2691,1418 2709,1418 2709,1354 2690,1335
  region net V_INPUT: 3590,630 3590,195 3525,130 3260,130 3200,190 3200,300 3020,480 2873,480 2873,630
  region net U2_SW: 3340,1355 3036.01,1355 2990,1308.99 2990,1210 3190,1210 3240,1260 3240,1293 3254,1307 3287,1307 3306,1326 3306,1337 3314,1345 3340,1345
  region net VBATT_SWITCHED: 3340,1405 3300,1405 3300,1450 3340,1450
  region net GND: 3140,1110 3140,970 3200,970 3200,1100 3190,1110
  region net GND: 2824.86,873.21 2962,873.21 2962,946 2847.65,946 2824.86,923.21
  region net GND: 3496.79,1464.86 3496.79,1604.86 3436.79,1604.86 3436.79,1474.86 3446.79,1464.86
  region net GND: 3512.76,1461.07 3512.76,1620.86 3458.98,1620.86 3458.98,1490.86 3488.76,1461.07
  region net GND: 2816.79,944.86 2816.79,1060 2762,1060 2762,949.65 2766.79,944.86
  region net GND: 3318,1331 3318,1301.95 3308,1292 3345,1258 3403,1258 3403,1288 3417,1302 3417,1331
  region net GND: 3365.49,1427.24 3365.49,1409.49 3364,1408 3367,1405 3448,1405 3451.14,1408.14 3451.14,1460.5 3446.79,1464.86
  region net 3V3_OUT: 3025,1865 3024,1864 3024,1780 3147,1780 3129,1798 3129,1849 3113,1865
  region net VIN2: 2610,1401.54 2610,1134 2662.03,1081.97 2662.03,668.97 2760.95,570.05 2759,504 2858.16,504 2858.16,563.84 2733,689 2733,1126 2691,1168 2691,1418 2678.48,1418 2662.02,1401.54
  region net V_Q1Q2: 2810,1356 2810,1575 2895,1660 3010,1660 3010,1757 2827.76,1757 2774,1757 2774,1659 2718,1600 2718,1356
  region net +3V3: 2997.82,1869.73 2653.73,1869.73 2539,1755 2539,1679 2586,1679 2689,1782 2998,1782
  region net VBATT: 2484,1075 2633,1075 2633,783 2620,770 2320,770 2320,911
  pour cut-out: 1888.69,408.29 1888.69,291.31 1906,274 1968.17,274 1968.17,194 2911.17,194 2911.17,406.86 2910.17,407.86 1888.17,407.86
  pour cut-out: 1887,2097 1887,1900 2915,1900 2915,2096
Mid-Layer 1:
  region net +3V3: 3000,1769.99 3000,1960 3021,1981 3170,1981 3170,2079.93 3101.16,2079.97 2958.49,2220 1960,2220 1910,2170 1910,2000 1980,2000 1980,2120 2010,2150 2880,2150 2930,2100 2930,1770
  region net VBATT: 2484,1075 2640,1075 2640,790 2620,770 2320,770 2320,911
  pour cut-out: 1888.69,408.29 1888.69,291.31 1906,274 1968.17,274 1968.17,194 2911.17,194 2911.17,406.86 2910.17,407.86 1888.17,407.86
  pour cut-out: 1887,2097 1887,1900 2915,1900 2915,2096
Bottom Layer:
  pour cut-out: 1888.69,408.29 1888.69,274 1968.17,274 1968.17,194 2911.17,194 2911.17,406.86 2910.17,407.86 1888.17,407.86
  pour cut-out: 1887,2097 1887,1900 2915,1900 2915,2096
  text ".Layer_Name" at 577,-858.49 h60

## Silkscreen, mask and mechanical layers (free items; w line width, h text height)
Top Overlay:
  text "3.3V" at 3239,1981 h60 r90
  text "GND" at 3611,1907 h60 r90
  text "BATT" at 2713,632 h60 r90
  text "+" at 3547,403 h100 r90
  text "2V - 3V" at 3485,170 h60 r90
  text ".PRJ_Number" at 570,60 h100
  text ".PCB_Rev" at 1170,60 h100
  text "©" at 1330,60 h105
  text ".CopyrightYear" at 1430,60 h100
  text "TI" at 1706,60 h100
  text ".Layer_Name" at 577,-858.49 h60
Bottom Overlay:
  text ".VersionControl_RevNumber" at 3070,90 h60
  text "SVN:" at 3340,90 h60
  text "MADE IN U.S." at 1347,81 h60
  text "UL94V-0" at 612,80 h60
  text ".Layer_Name" at 577,-858.49 h60
Top Paste:
  text ".Layer_Name" at 577,-858.49 h60
Bottom Paste:
  text ".Layer_Name" at 577,-858.49 h60
Top Solder:
  text ".Layer_Name" at 577,-858.49 h60
  text ".Layer_Name" at 577,-858.49 h60
Bottom Solder:
  text ".Layer_Name" at 577,-858.49 h60
Drill Guide:
  text ".Layer_Name" at 577,-858.49 h60
M1 Board Outline:
  the board outline again, w10
  text ".Layer_Name" at 577,-858.49 h60
M2 Board Dimensions:
  rectangle: 0,-275 125,-150
  rectangle: 125,-400 500,-275
  lines w7: 0,-275 1000,-275 ; 125,-400 125,-150 ; 250,-400 250,-150 ; 500,-400 500,-150 ; 750,-400 750,-150 ; 0,-400 1000,-400 1000,-150 0,-150 0,-400
  text ".Layer_Name" at 577,-858.49 h60
M3 3D STEP Top:
  text ".Layer_Name" at 577,-858.49 h60
M4 3D STEP Bottom:
  text ".Layer_Name" at 577,-858.49 h60
M5 Assembly Top:
  lines w10: -292,-930.17 6308,-930.17 ; -292,-726.83 6310,-726.83 ; -292,-523.5 -292,-1133.5 3713,-1133.5 6310,-1133.5 6310,-523.5 -291.5,-523.5 -291.5,-1133.5 1284,-1133.5 ; 2173,-1133.5 2173,-523.5 ; 3440,-726.83 3440,-523.5 ; 4280,-726.83 4280,-523.5 ; 4902,-1140 4902,-937.17
  text "COMPONENTS MARKED 'DNP' SHOULD NOT BE POPULATED." at 1153.5,-318.5 h60
  text "ASSEMBLY VARIANT:" at 1153,-434 h60
  text ".VariantName" at 2189,-434 h60
  text "PCB VIEWED FROM TOP SIDE" at -228.5,-655.67 h60
  text "BOARD #:" at 2248,-655.67 h60
  text ".PRJ_Number" at 2793.5,-655.67 h60
  text "REV:" at 3638,-655.67 h60
  text ".PCB_Rev" at 3929.5,-655.67 h60
  text "SVN REV:" at 4476,-655.67 h60
  text ".VersionControl_RevNumber" at 4982,-655.67 h60
  text "PLOT NAME =" at -228.5,-1064.34 h60
  text ".plot_File_Name" at 577,-1064.34 h60
  text "GENERATED    :" at 2250,-1064.34 h60
  text ".Print_Date" at 3119.5,-1064.34 h60
  text ".Print_Time" at 3848.5,-1064.34 h60
  text "TEXAS INSTRUMENTS" at 5113,-1064.34 h60
M6 Assembly Bottom:
  lines w10: -292.5,-727.33 6309.5,-727.33 ; -290.5,-930.67 6309.5,-930.67 ; 1115.5,-1140.5 1115.5,-937.67 ; 1737.5,-727.33 1737.5,-524 ; 2577.5,-727.33 2577.5,-524 ; 3844.5,-1134 3844.5,-524 ; 4733.5,-1134 6309,-1134 6309,-524 -292.5,-524 -292.5,-1134 2304.5,-1134 6309.5,-1134 6309.5,-524
  text "COMPONENTS MARKED 'DNP' SHOULD NOT BE POPULATED." at 6102,-318 h60
  text ".VariantName" at 5058,-434 h60
  text "ASSEMBLY VARIANT:" at 6097,-434 h60
  text ".VersionControl_RevNumber" at 1035.5,-656.17 h60
  text "SVN REV:" at 1541.5,-656.17 h60
  text ".PCB_Rev" at 2088,-656.17 h60
  text "REV:" at 2379.5,-656.17 h60
  text ".PRJ_Number" at 3224,-656.17 h60
  text "BOARD #:" at 3769.5,-656.17 h60
  text "PCB VIEWED FROM BOTTOM SIDE" at 6246,-656.17 h60
  text "TEXAS INSTRUMENTS" at 904.5,-1064.84 h60
  text ".Print_Time" at 2169,-1064.84 h60
  text ".Print_Date" at 2898,-1064.84 h60
  text "GENERATED    :" at 3767.5,-1064.84 h60
  text ".plot_File_Name" at 5440.5,-1064.84 h60
  text "PLOT NAME =" at 6246,-1064.84 h60
M9 Title Sheet:
  drawing of 57 lines, arcs and shapes, not listed
  text "1" at 739.84,8036.5 h70
  text "2" at 3235.5,8036.5 h70
  text "3" at 5724.84,8036.5 h70
  text "4" at 8231.51,8036.5 h70
  text "5" at 10730.5,8036.5 h70
  text "6" at 13235.5,8036.5 h70
  text "A" at -416.5,6893.5 h70
  text "A" at 14383.5,6893.5 h70
  text "B" at -416.5,4513.5 h70
  text "B" at 14383.5,4513.5 h70
  text "C" at -416.5,2138.5 h70
  text "C" at 14383.5,2138.5 h70
  text "PROJECT TITLE:" at 11343.5,277.5 h45
  text ".PRJ_Title" at 11393.5,144.17 h60
  text "DESIGNED FOR:" at 11343.5,-23.5 h45
  text ".PRJ_Customer" at 11393.5,-163.5 h70
  text "D" at -416.5,-231.5 h70
  text "D" at 14383.5,-231.5 h70
  text "FILE NAME:" at 11343.5,-323.5 h45
  text ".PCB_File_Name_No_Path" at 11393.5,-443.5 h70
  text "Texas Instruments (TI) and/or its licensors do not warrant the accuracy or completeness of this specification" at 6374,-605.34 h45
  text "ENGINEER:" at 11343.5,-613.5 h45
  text "LAYOUT BY:" at 12848.5,-613.5 h45
  text "or any information contained therein. TI and/or its licensors do not warrant that this design will meet" at 6329.01,-718 h45
  text ".PRJ_Engineer" at 11393.5,-768.49 h70
  text ".PCB_Layout" at 12899,-768.49 h70
  text "the specifications, will be suitable for your application or fit for any particular purpose, or will operate in" at 6329.01,-830.67 h45
  text ".Layer_Name" at 577,-858.49 h60
  text "ALTIUM DESIGNER VERSION:" at 12848.5,-923.5 h45
  text "an implementation. TI and/or its licensors do not warrant that the design is production worthy. You should" at 6329.01,-943.33 h45
  text "completely validate and test your design implementation to confirm the system functionality for your application." at 6374,-1056 h45
  text ".print_Scale" at 11393.5,-1056.83 h70
  text ".Application_BuildNumber" at 12899,-1056.83 h70
  text "1" at 739.84,-1263.5 h70
  text "2" at 3235.5,-1263.5 h70
  text "3" at 5724.84,-1263.5 h70
  text "4" at 8231.51,-1263.5 h70
  text "5" at 10730.5,-1263.5 h70
  text "6" at 13235.5,-1263.5 h70
M10 Fab Notes:
  drawing of 185 lines, arcs and shapes, not listed
  text "DESIGN INFORMATION" at 12381.02,5910 h60
  text "MIN. TRACK WIDTH:" at 11736.46,5730 h60
  text "8" at 12832.7,5730 h60
  text "MIL" at 12987.46,5730 h60
  text "MIN. CLEARANCE:" at 11736.46,5598 h60
  text "0.2" at 12772.7,5598 h60
  text "mm" at 12987.46,5598 h60
  text "MIN. VIA PAD SIZE:" at 11736.46,5466 h60
  text "22" at 12802.71,5466 h60
  text "MIL" at 12987.46,5466 h60
  text "0.05mm (2MIL)" at 12431.46,5324.29 h60
  text "MINIMUM ANNULAR RING" at 11407.23,5320 h60
  text "EXTERNAL" at 13139.46,5320 h60
  text "PER" at 11607.23,5202 h60
  text "IPC-D-275 CLASS 2 LEVEL C" at 11827.23,5202 h60
  text "MIL, HOLES" at 13315.46,5089.71 h60
  text "+/-" at 12923,5089 h60
  text "+/-" at 13777,5089 h60
  text "REGISTRATION TOLERANCES:" at 11407.23,5084 h60
  text "METAL" at 12607,5084 h60
  text "5" at 13183.2,5084 h60
  text "3" at 14016.2,5084 h60
  text "MIL" at 14132.46,5084 h60
  text "MATERIAL:" at 11332.46,4874.54 h60
  text "FR-4 High Tg" at 12318.9,4734.21 h60
  text "FR-408" at 11753.46,4725.64 h60
  text "X" at 12165.46,4725.64 h60
  text "OTHER" at 13241.46,4725.64 h60
  text "62 MIL (1.6mm) +/-10%" at 12073.56,4562.92 h60
  text "THICKNESS:" at 11407.23,4558.64 h60
  text "X" at 11945.4,4558.64 h60
  text "OTHER" at 13358.46,4558.64 h60
  text "TOLERANCE:" at 11407.23,4400.64 h60
  text "X" at 12246.53,4400.64 h60
  text "ANSI IPC-6012 TYPE 3 CLASS 2" at 12433.48,4400.64 h60
  text "OTHER +/-" at 12433.46,4244.64 h60
  text "BOW & TWIST:" at 11407.23,4087.64 h60
  text "X" at 12246.53,4087.64 h60
  text "ANSI IPC-6012 TYPE 3 CLASS 2" at 12433.48,4087.64 h60
  text "OTHER +/-" at 12433.46,3929.13 h60
  text "DRILLING:" at 11332.46,3790.64 h60
  text "REFERENCE:" at 11407.23,3673.64 h60
  text "X" at 12055.46,3673.64 h60
  text "AS SHOWN" at 12242.46,3673.64 h60
  text "X" at 12956.46,3673.64 h60
  text "NC_DRILL FILES" at 13093.46,3673.64 h60
  text "PTH MIN COPPER THICKNESS:" at 11407.23,3515.64 h60
  text "X" at 12757.46,3515.64 h60
  text "1MIL" at 12894.46,3515.64 h60
  text "OTHER" at 13391.46,3515.64 h60
  text "BOARD FINISH:" at 11332.46,3356.64 h60
  text "SILKSCREEN:" at 11487.68,3238.64 h60
  text "X" at 12436.46,3238.64 h60
  text "TOP" at 12562.46,3238.64 h60
  text "X" at 12946.46,3238.64 h60
  text "BOTTOM" at 13073.46,3238.64 h60
  text "SILKSCREEN COLOR:" at 11487.68,3071.64 h60
  text "X" at 12435.42,3071.64 h60
  text "WHITE" at 12562.46,3071.64 h60
  text "OTHER" at 13073.46,3071.64 h60
  text "SOLDER RESIST COLOR:" at 11487.68,2901.64 h60
  text "X" at 12055.42,2742.44 h60
  text "GREEN" at 12182.46,2742.44 h60
  text "BLUE" at 12773.46,2742.44 h60
  text "OTHER" at 13311.46,2742.44 h60
  text "IMMERSION GOLD (ENIG)" at 12393.46,2553.92 h60
  text "ENEPIG" at 13731,2550.64 h60
  text "SURFACE FINISH:" at 11332.46,2549.64 h60
  text "X" at 12206.51,2549.64 h60
  text "IMM. TIN/SILVER OR EQUIV" at 11662,2392.64 h60
  text "OTHER" at 13093.46,2392.64 h60
  text "ARRAY/PANEL:" at 11332.46,2213.64 h60
  text "CUT AND TRIM PER MECH LAYER 1" at 12393.46,2209.35 h60
  text "N.C. ROUTE" at 12393.46,2057.64 h60
  text "X" at 13072.46,2057.64 h60
  text "V. SCORE" at 13259.46,2057.64 h60
  text "CERTIFICATION:" at 11332.46,1920.64 h60
  text "MATERIALS AND WORKMANSHIP FOR ALL PCBS" at 12057.46,1920.64 h60
  text "TO MEET OR EXCEED THE REQUIREMENTS OF:" at 12057.46,1822.64 h60
  text "X" at 11683.96,1686.13 h60
  text "ANSI IPC-A-600F CLASS ->" at 11822.96,1686.13 h60
  text "X" at 13462.02,1686.13 h60
  text "2" at 13580.96,1686.14 h60
  text "1" at 13265.96,1684.64 h60
  text "3" at 13934.96,1684.64 h60
  text "X" at 11686.02,1526.64 h60
  text "UL 94V-0" at 11822.96,1526.64 h60
  text "X" at 12498.02,1526.64 h60
  text "RoHS" at 12634.96,1526.64 h60
  text "OTHER" at 13279.36,1526.64 h60
  text "PER ORDER" at 13676.42,1526.64 h60
  text "ADDITIONAL REQUIREMENTS:" at 11332.46,1385.64 h60
  text "MICROSECTION:" at 11407.23,1270.64 h60
  text "YES" at 12312.96,1270.64 h60
  text "REQUIRED" at 13174.46,1114.49 h60
  text "BARE BOARD ELEC. TEST:" at 11407.23,1111.64 h60
  text "NONE" at 12712.96,1111.64 h60
  text "X" at 13047.46,1111.64 h60
  text "PER ORDER" at 13766.46,1111.64 h60
  text "MANUFACTURER'S UL:" at 11407.23,954.64 h60
  text "RAIL" at 12572.96,950.35 h60
  text "METAL" at 13064.77,950.35 h60
  text "X" at 13440,950 h60
  text "SILK" at 13576.46,950.35 h60
  text ".Layer_Name" at 577,-858.49 h60
M11 Gerber Information:
  lines w10: -292,-930.17 6308,-930.17 ; -292,-726.83 6310,-726.83 ; -292,-523.5 -292,-1133.5 3713,-1133.5 6310,-1133.5 6310,-523.5 -291.5,-523.5 -291.5,-1133.5 1284,-1133.5 ; 2173,-1133.5 2173,-523.5 ; 3440,-726.83 3440,-523.5 ; 4280,-726.83 4280,-523.5 ; 4902,-1140 4902,-937.17
  text "ALL ARTWORK VIEWED FROM TOP SIDE" at -228.5,-655.67 h60
  text "BOARD #:" at 2248,-655.67 h60
  text ".PRJ_Number" at 2793.5,-655.67 h60
  text "REV:" at 3638,-655.67 h60
  text ".PCB_Rev" at 3929.5,-655.67 h60
  text "SVN REV:" at 4476,-655.67 h60
  text ".VersionControl_RevNumber" at 4982,-655.67 h60
  text "LAYER NAME =" at -228.5,-858.49 h60
  text "PLOT NAME =" at -228.5,-1064.34 h60
  text ".plot_File_Name" at 577,-1064.34 h60
  text "GENERATED    :" at 2250,-1064.34 h60
  text ".Print_Date" at 3119.5,-1064.34 h60
  text ".Print_Time" at 3848.5,-1064.34 h60
  text "TEXAS INSTRUMENTS" at 5113,-1064.34 h60
M12 Stackup:
  drawing of 296 lines, arcs and shapes, not listed
  text "Layer" at 9702,7831 h60
  text "Name" at 10111.91,7831 h60
  text "Material" at 11131.63,7831 h60
  text "Thickness" at 11991.4,7831 h60
  text "Constant" at 12641.23,7831 h60
  text "Board Layer Stack" at 13211.09,7831 h60
  text "1" at 9702,7711 h60
  text "Top Overlay" at 10111.91,7711 h60
  text "2" at 9702,7591 h60
  text "Top Solder" at 10111.91,7591 h60
  text "Solder Resist" at 11131.63,7591 h60
  text "0.40mil" at 11991.4,7591 h60
  text "3.5" at 12641.23,7591 h60
  text "3" at 9702,7471 h60
  text "Top Layer" at 10111.91,7471 h60
  text "Copper" at 11131.63,7471 h60
  text "2.00mil" at 11991.4,7471 h60
  text "4" at 9702,7351 h60
  text "Dielectric1" at 10111.91,7351 h60
  text "FR-4 High Tg" at 11131.63,7351 h60
  text "9.65mil" at 11991.4,7351 h60
  text "4.8" at 12641.23,7351 h60
  text "5" at 9702,7231 h60
  text "Internal Plane 1" at 10111.91,7231 h60
  text "Copper" at 11131.63,7231 h60
  text "1.40mil" at 11991.4,7231 h60
  text "6" at 9702,7111 h60
  text "Dielectric3" at 10111.91,7111 h60
  text "FR-4 High Tg" at 11131.63,7111 h60
  text "36.00mil" at 11991.4,7111 h60
  text "4.8" at 12641.23,7111 h60
  text "7" at 9702,6991 h60
  text "Mid-Layer 1" at 10111.91,6991 h60
  text "Copper" at 11131.63,6991 h60
  text "1.40mil" at 11991.4,6991 h60
  text "8" at 9702,6871 h60
  text "Dielectric2" at 10111.91,6871 h60
  text "FR-4 High Tg" at 11131.63,6871 h60
  text "9.65mil" at 11991.4,6871 h60
  text "4.8" at 12641.23,6871 h60
  text "9" at 9702,6751 h60
  text "Bottom Layer" at 10111.91,6751 h60
  text "Copper" at 11131.63,6751 h60
  text "2.00mil" at 11991.4,6751 h60
  text "10" at 9702,6631 h60
  text "Bottom Solder" at 10111.91,6631 h60
  text "Solder Resist" at 11131.63,6631 h60
  text "0.40mil" at 11991.4,6631 h60
  text "3.5" at 12641.23,6631 h60
  text "11" at 9702,6511 h60
  text "Bottom Overlay" at 10111.91,6511 h60
  text ".Layer_Name" at 577,-858.49 h60
M13 Component Bodies Top:
  text ".Layer_Name" at 577,-858.49 h60
M14 Component Bodies Bottom:
  text ".Layer_Name" at 577,-858.49 h60
M15 Courtyards Top:
  text ".Layer_Name" at 577,-858.49 h60
M16 Courtyards Bottom:
  text ".Layer_Name" at 577,-858.49 h60
Drill Drawing:
  circle w10: c4383.9,1851.28 r20.77
  lines w10: 4363.13,978.91 4383.9,958.14 4404.67,978.91 4383.9,999.68 4363.13,978.91 ; 4363.13,1082.76 4363.13,1093.15 4373.51,1103.53 4363.13,1113.92 4363.13,1124.3 4373.51,1124.3 4383.9,1113.92 4394.29,1124.3 4404.67,1124.3 4404.67,1113.92 4394.29,1103.53 4404.67,1093.15 4404.67,1082.76 4394.29,1082.76 4383.9,1093.15 4373.51,1082.76 4363.13,1082.76 ; 4363.13,1217.77 4373.51,1217.77 4373.51,1207.39 4394.29,1207.39 4394.29,1217.77 4404.67,1217.77 4404.67,1238.54 4394.29,1238.54 4394.29,1248.93 4373.51,1248.93 4373.51,1238.54 4363.13,1238.54 4363.13,1217.77 ; 4363.13,1332.01 4383.9,1342.4 4404.67,1332.01 4394.29,1352.78 4404.67,1373.55 4383.9,1363.17 4363.13,1373.55 4373.51,1352.78 4363.13,1332.01 ; 4363.13,1467.02 4373.51,1467.02 4383.9,1456.64 4394.29,1467.02 4404.67,1467.02 4394.29,1477.41 4404.67,1487.79 4394.29,1487.79 4383.9,1498.18 4373.51,1487.79 4363.13,1487.79 4373.51,1477.41 4363.13,1467.02 ; 4363.13,1622.8 4404.67,1622.8 4383.9,1581.26 4363.13,1622.8 ; 4363.13,1705.89 4404.67,1705.89 4404.67,1747.43 4363.13,1747.43 4363.13,1705.89 ; 4363.13,1955.14 4404.67,1955.14 4404.67,1996.68 4363.13,1996.68 4363.13,1955.14 ; 4371.44,1714.2 4396.36,1714.2 4396.36,1739.12 4371.44,1739.12 4371.44,1714.2
  lines w12: 4306,920.75 6334.89,920.75 ; 4306,2042.38 6334.89,2042.38 ; 4654.12,796.12 4654.12,2167 ; 4996.36,796.12 4996.36,2167 ; 5642.91,796.12 5642.91,2167 ; 5912.19,796.12 5912.19,2167 ; 4306,796.12 6334.89,796.12 6334.89,2167 4306,2167 4306,796.12
  text "Symbol" at 4380.77,2079.76 h72
  text "Quantity" at 4691.51,2079.76 h72
  text "Finished Hole Size" at 5033.74,2079.76 h72
  text "Plated" at 5680.3,2079.76 h72
  text "Hole Type" at 5949.57,2079.76 h72
  text "4" at 4691.51,1955.14 h60
  text "7.87mil (0.200mm)" at 5033.74,1955.14 h60
  text "PTH" at 5680.3,1955.14 h60
  text "Round" at 5949.57,1955.14 h60
  text "288" at 4691.51,1830.51 h60
  text "10.00mil (0.254mm)" at 5033.74,1830.51 h60
  text "PTH" at 5680.3,1830.51 h60
  text "Round" at 5949.57,1830.51 h60
  text "1" at 4691.51,1705.89 h60
  text "12.00mil (0.305mm)" at 5033.74,1705.89 h60
  text "PTH" at 5680.3,1705.89 h60
  text "Round" at 5949.57,1705.89 h60
  text "12" at 4691.51,1581.26 h60
  text "40.00mil (1.016mm)" at 5033.74,1581.26 h60
  text "PTH" at 5680.3,1581.26 h60
  text "Round" at 5949.57,1581.26 h60
  text "40" at 4691.51,1456.64 h60
  text "45.28mil (1.150mm)" at 5033.74,1456.64 h60
  text "PTH" at 5680.3,1456.64 h60
  text "Round" at 5949.57,1456.64 h60
  text "2" at 4691.51,1332.01 h60
  text "50.00mil (1.270mm)" at 5033.74,1332.01 h60
  text "PTH" at 5680.3,1332.01 h60
  text "Round" at 5949.57,1332.01 h60
  text "2" at 4691.51,1207.39 h60
  text "51.18mil (1.300mm)" at 5033.74,1207.39 h60
  text "PTH" at 5680.3,1207.39 h60
  text "Round" at 5949.57,1207.39 h60
  text "4" at 4691.51,1082.76 h60
  text "98.43mil (2.500mm)" at 5033.74,1082.76 h60
  text "PTH" at 5680.3,1082.76 h60
  text "Round" at 5949.57,1082.76 h60
  text "2" at 4691.51,958.14 h60
  text "139.76mil (3.550mm)" at 5033.74,958.14 h60
  text "PTH" at 5680.3,958.14 h60
  text "Round" at 5949.57,958.14 h60
  text "355 Total" at 4691.51,833.51 h60
  text ".Layer_Name" at 577,-858.49 h60

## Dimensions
0,-400 to 1000,-400 on M2 Board Dimensions
0,0 to 0,2300 on M2 Board Dimensions
0,0 to 3700,0 on M2 Board Dimensions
